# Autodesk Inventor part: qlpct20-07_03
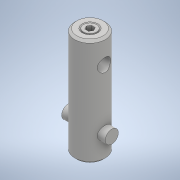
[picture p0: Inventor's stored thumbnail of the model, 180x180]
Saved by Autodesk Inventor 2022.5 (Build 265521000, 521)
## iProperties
Part Number: qlpct20-07_03
Material: 一般
Document SubType Name: Modeling
Designer: ImaoCorp
Density: 1 g/cm^3
Appearance: 既定
Author: ImaoCorp
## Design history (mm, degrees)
feature "qlpct20-07_03"
node "ソリッド1"
